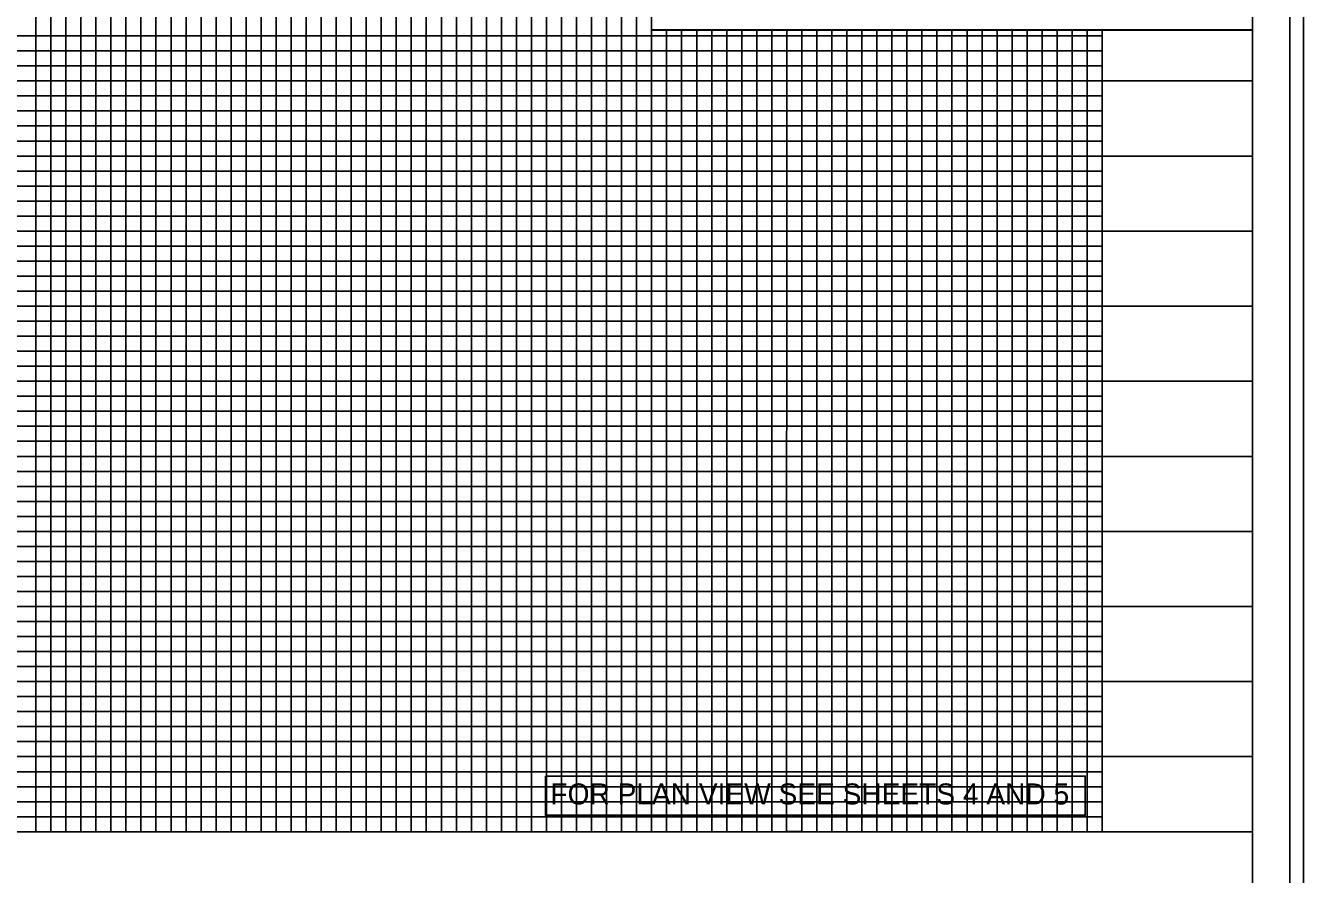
# Model space of a CAD drawing. Extents: x 1755181 to 1757273, y 729911 to 735411.
# Drawn here: x 1756439.2 to 1756864.7, y 732671.6 to 732954.2 of the extents above; entities that cross this region are included whole.
import ezdxf

# ---------------------------------------------------------------- set-up
doc = ezdxf.new("R2010")
doc.units = 0
for name, color, linetype in [('Old_Level_43', 7, 'Continuous'), ('Prop Grid Mask', 7, 'Continuous'), ('Prop VPI Label', 7, 'Continuous'), ('Scratch_Level_3', 7, 'Continuous'), ('Sheet DOT Grid CELL', 7, 'Continuous'), ('Sheet Plot Border Inside CELL', 7, 'Continuous'), ('Sheet Plot Border Outside CELL', 7, 'Continuous'), ('Sheet Profile CELL', 7, 'Continuous'), ('Sheet Profile Grid Major CELL', 7, 'Continuous'), ('Sheet Profile Grid Middle CELL', 7, 'Continuous'), ('Sheet Profile Grid Minor CELL', 7, 'Continuous')]:
    doc.layers.add(name, color=color, linetype=linetype)

msp = doc.modelspace()

# ---------------------------------------------------------------- linework, layer by layer
at = {"layer": 'Old_Level_43'}
msp.add_lwpolyline([(1756847.68, 732952.66), (1756647.63, 732952.66), (1756647.63, 732989.43)], dxfattribs=at)
at = {"layer": 'Prop Grid Mask'}
msp.add_lwpolyline([(1756612.34, 732704.29), (1756792.01, 732704.29), (1756792.01, 732691.28), (1756612.34, 732691.28)], close=True, dxfattribs=at)
at = {"layer": 'Scratch_Level_3'}
msp.add_lwpolyline([(1755347.67, 732660.78), (1755347.67, 733185.78), (1756647.65, 733185.78), (1756647.63, 732952.8), (1756847.67, 732952.8), (1756847.67, 732660.78)], close=True, dxfattribs=at)
at = {"layer": 'Sheet DOT Grid CELL'}
for p, q in [((1756447.67, 732685.78), (1756447.67, 733185.78)), ((1756497.67, 732685.78), (1756497.67, 733185.78)), ((1756547.67, 732685.78), (1756547.67, 733185.78)), ((1756597.67, 732685.78), (1756597.67, 733185.78)), ((1756647.67, 732685.78), (1756647.67, 733048.23)), ((1756697.67, 732685.78), (1756697.67, 732952.66)), ((1756747.67, 732685.78), (1756747.67, 732952.66)), ((1756797.67, 732685.78), (1756797.67, 732952.66)), ((1756847.67, 732935.78), (1755347.67, 732935.78)), ((1756847.67, 732885.78), (1755347.67, 732885.78)), ((1756847.67, 732835.78), (1755347.67, 732835.78)), ((1756847.67, 732785.78), (1755347.67, 732785.78)), ((1756847.67, 732735.78), (1755347.67, 732735.78))]:
    msp.add_line(p, q, dxfattribs=at)
at = {"layer": 'Sheet Plot Border Inside CELL'}
msp.add_lwpolyline([(1755193.67, 732133.23), (1756860.17, 732133.23), (1756860.17, 733188.33), (1755193.67, 733188.33)], close=True, dxfattribs=at)
at = {"layer": 'Sheet Plot Border Outside CELL'}
msp.add_lwpolyline([(1755180.67, 732110.78), (1756864.67, 732110.78), (1756864.67, 733210.78), (1755180.67, 733210.78)], close=True, dxfattribs=at)
at = {"layer": 'Sheet Profile CELL'}
msp.add_line((1755347.67, 732685.78), (1756847.67, 732685.78), dxfattribs=at)
msp.add_lwpolyline([(1756847.67, 733185.78), (1755347.67, 733185.78), (1755347.67, 732135.78), (1756847.67, 732135.78)], close=True, dxfattribs=at)
at = {"layer": 'Sheet Profile Grid Major CELL'}
msp.add_line((1756747.67, 732685.78), (1756747.67, 732685.78), dxfattribs=at)
for points in [[(1756397.67, 732685.78), (1756447.67, 732685.78), (1756447.67, 733185.78), (1756497.67, 733185.78), (1756497.67, 732685.78), (1756547.67, 732685.78), (1756547.67, 733185.78), (1756597.67, 733185.78), (1756597.67, 732685.78), (1756647.67, 732685.78), (1756647.67, 733185.78), (1756673.97, 733185.78)], [(1756797.67, 732952.66), (1756797.67, 732685.78), (1756847.67, 732685.78), (1756847.67, 733035.78)], [(1756647.63, 732985.78), (1755347.67, 732985.78), (1755347.67, 732935.78), (1756847.67, 732935.78)], [(1756697.67, 732952.66), (1756697.67, 732685.78), (1756747.67, 732685.78), (1756747.67, 732685.78), (1756747.67, 732952.66)], [(1756847.67, 732885.78), (1755347.67, 732885.78), (1755347.67, 732835.78), (1756847.67, 732835.78)], [(1756847.67, 732785.78), (1755347.67, 732785.78), (1755347.67, 732785.78), (1755347.67, 732735.78), (1756847.67, 732735.78)]]:
    msp.add_lwpolyline(points, dxfattribs=at)
at = {"layer": 'Sheet Profile Grid Middle CELL'}
for points in [[(1756422.67, 732685.78), (1756472.67, 732685.78), (1756472.67, 733185.78), (1756522.67, 733185.78), (1756522.67, 732685.78), (1756572.67, 732685.78), (1756572.67, 733185.78), (1756622.67, 733185.78), (1756622.67, 732685.78), (1756672.67, 732685.78), (1756672.67, 732952.66)], [(1756672.67, 732948.58), (1756672.67, 732685.78), (1756722.67, 732685.78), (1756722.67, 732952.66)], [(1756722.67, 732948.58), (1756722.67, 732685.78), (1756772.67, 732685.78), (1756772.67, 732952.66)], [(1756847.67, 732910.78), (1755347.67, 732910.78), (1755347.67, 732860.78), (1756847.67, 732860.78)], [(1756847.67, 732810.78), (1755347.67, 732810.78), (1755347.67, 732760.78), (1756847.67, 732760.78)], [(1756847.67, 732710.78), (1755347.67, 732710.78)]]:
    msp.add_lwpolyline(points, dxfattribs=at)
at = {"layer": 'Sheet Profile Grid Minor CELL'}
for p, q in [((1756797.67, 732950.78), (1755397.67, 732950.78)), ((1755397.67, 732945.78), (1756797.67, 732945.78)), ((1756797.67, 732940.78), (1755397.67, 732940.78)), ((1755397.67, 732930.78), (1756797.67, 732930.78)), ((1756797.67, 732925.78), (1755397.67, 732925.78)), ((1755397.67, 732920.78), (1756797.67, 732920.78)), ((1756797.67, 732915.78), (1755397.67, 732915.78)), ((1755397.67, 732905.78), (1756797.67, 732905.78)), ((1756797.67, 732900.78), (1755397.67, 732900.78)), ((1755397.67, 732895.78), (1756797.67, 732895.78)), ((1756797.67, 732890.78), (1755397.67, 732890.78)), ((1755397.67, 732880.78), (1756797.67, 732880.78)), ((1756797.67, 732875.78), (1755397.67, 732875.78)), ((1755397.67, 732870.78), (1756797.67, 732870.78)), ((1756797.67, 732865.78), (1755397.67, 732865.78)), ((1755397.67, 732855.78), (1756797.67, 732855.78)), ((1756797.67, 732850.78), (1755397.67, 732850.78)), ((1755397.67, 732845.78), (1756797.67, 732845.78)), ((1756797.67, 732840.78), (1755397.67, 732840.78)), ((1755397.67, 732830.78), (1756797.67, 732830.78)), ((1756797.67, 732825.78), (1755397.67, 732825.78)), ((1755397.67, 732820.78), (1756797.67, 732820.78)), ((1756797.67, 732815.78), (1755397.67, 732815.78)), ((1755397.67, 732805.78), (1756797.67, 732805.78)), ((1756797.67, 732800.78), (1755397.67, 732800.78)), ((1756797.67, 732795.78), (1755397.67, 732795.78)), ((1756797.67, 732790.78), (1755397.67, 732790.78)), ((1755397.67, 732780.78), (1756797.67, 732780.78)), ((1756797.67, 732775.78), (1755397.67, 732775.78)), ((1755397.67, 732770.78), (1756797.67, 732770.78)), ((1756797.67, 732765.78), (1755397.67, 732765.78)), ((1755397.67, 732755.78), (1756797.67, 732755.78)), ((1756797.67, 732750.78), (1755397.67, 732750.78)), ((1755397.67, 732745.78), (1756797.67, 732745.78)), ((1756797.67, 732740.78), (1755397.67, 732740.78)), ((1755397.67, 732730.78), (1756797.67, 732730.78)), ((1756797.67, 732725.78), (1755397.67, 732725.78)), ((1755397.67, 732720.78), (1756797.67, 732720.78)), ((1756797.67, 732715.78), (1755397.67, 732715.78)), ((1755397.67, 732705.78), (1756797.67, 732705.78)), ((1756797.67, 732700.78), (1755397.67, 732700.78)), ((1755397.67, 732695.78), (1756797.67, 732695.78)), ((1756797.67, 732690.78), (1756797.67, 732690.78))]:
    msp.add_line(p, q, dxfattribs=at)
for points in [[(1756437.67, 732685.78), (1756442.67, 732685.78), (1756442.67, 733185.78)], [(1756452.67, 733185.78), (1756452.67, 732685.78), (1756457.67, 732685.78), (1756457.67, 733185.78)], [(1756462.67, 733185.78), (1756462.67, 732685.78), (1756467.67, 732685.78), (1756467.67, 733185.78)], [(1756477.67, 733185.78), (1756477.67, 732685.78), (1756482.67, 732685.78), (1756482.67, 733185.78)], [(1756487.67, 733185.78), (1756487.67, 732685.78), (1756492.67, 732685.78), (1756492.67, 733185.78)], [(1756502.67, 733185.78), (1756502.67, 732685.78), (1756507.67, 732685.78), (1756507.67, 733185.78)], [(1756512.67, 733185.78), (1756512.67, 732685.78), (1756517.67, 732685.78), (1756517.67, 733185.78)], [(1756527.67, 733185.78), (1756527.67, 732685.78), (1756532.67, 732685.78), (1756532.67, 733185.78)], [(1756537.67, 733185.78), (1756537.67, 732685.78)], [(1756537.67, 732685.78), (1756542.67, 732685.78), (1756542.67, 733185.78)], [(1756552.67, 733185.78), (1756552.67, 732685.78), (1756557.67, 732685.78), (1756557.67, 733185.78)], [(1756562.67, 733185.78), (1756562.67, 732685.78), (1756567.67, 732685.78), (1756567.67, 733185.78)], [(1756577.67, 733185.78), (1756577.67, 732685.78), (1756582.67, 732685.78), (1756582.67, 733185.78)], [(1756587.67, 733185.78), (1756587.67, 732685.78), (1756592.67, 732685.78), (1756592.67, 733185.78)], [(1756602.67, 733185.78), (1756602.67, 732685.78), (1756607.67, 732685.78), (1756607.67, 733185.78)], [(1756612.67, 733185.78), (1756612.67, 732685.78), (1756617.67, 732685.78), (1756617.67, 733185.78)], [(1756627.67, 733185.78), (1756627.67, 732685.78), (1756632.67, 732685.78), (1756632.67, 733185.78)], [(1756637.67, 733185.78), (1756637.67, 732685.78), (1756642.67, 732685.78), (1756642.67, 733185.78)], [(1756652.67, 732952.66), (1756652.67, 732685.78), (1756657.67, 732685.78), (1756657.67, 732952.66)], [(1756662.67, 732952.66), (1756662.67, 732685.78), (1756667.67, 732685.78), (1756667.67, 732952.66)], [(1756677.67, 732952.66), (1756677.67, 732685.78), (1756677.67, 732685.78), (1756682.67, 732685.78), (1756687.67, 732685.78), (1756687.67, 732952.66)], [(1756682.67, 732952.66), (1756682.67, 732685.78)], [(1756692.64, 732952.66), (1756692.57, 732685.83), (1756697.57, 732685.83), (1756702.67, 732685.78), (1756702.67, 732952.66)], [(1756702.67, 732948.58), (1756702.67, 732685.78), (1756707.67, 732685.78), (1756707.67, 732952.66)], [(1756712.67, 732952.66), (1756712.67, 732685.78), (1756717.67, 732685.78), (1756717.67, 732952.66)], [(1756727.67, 732952.66), (1756727.67, 732685.78), (1756732.67, 732685.78), (1756732.67, 732952.66)], [(1756737.67, 732952.66), (1756737.67, 732685.78), (1756742.67, 732685.78), (1756742.67, 732952.66)], [(1756752.67, 732952.66), (1756752.67, 732685.78), (1756757.67, 732685.78), (1756757.67, 732952.66)], [(1756762.67, 732952.66), (1756762.67, 732685.78), (1756767.67, 732685.78), (1756767.67, 732952.66)], [(1756777.67, 732952.66), (1756777.67, 732685.78), (1756782.67, 732685.78), (1756782.67, 732952.66)], [(1756787.67, 732952.66), (1756787.67, 732685.78), (1756792.67, 732685.78), (1756792.67, 732952.66)], [(1756797.67, 732690.78), (1755397.67, 732690.78)]]:
    msp.add_lwpolyline(points, dxfattribs=at)

# ---------------------------------------------------------------- texts
at = {"layer": 'Prop VPI Label'}
msp.add_text('FOR PLAN VIEW SEE SHEETS 4 AND 5', height=7, dxfattribs=at).set_placement((1756613.98, 732694.86))

doc.saveas('drawing.dxf')
